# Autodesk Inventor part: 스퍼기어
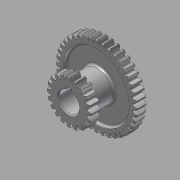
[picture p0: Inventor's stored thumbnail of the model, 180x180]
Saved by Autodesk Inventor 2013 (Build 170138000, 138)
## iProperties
Created: 2015-09
Part Number: 스퍼기어
Material: 강철, 연강
Document SubType Name: Modeling
Designer: mduedu
Density: 1 g/cm^3
Author: mduedu
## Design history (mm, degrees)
sketch "스케치1"
  geometry: C1 r 38 at (0, 0); C2 r 40 at (0, 0); C3 r 35.5 at (0, 0); 1 further point
  constraints: 3 centre point, 3 coincident
  dimensions: "d0" = 76 diameter of C1; "d2" = 2 radial gap between concentric circles of C2 C1; "d3" = 71 diameter of C3 (computed from d0)
extrude "돌출1" new body sketch "스케치1" stored distance "d4" = 10; taper "d5" = 0 deg
sketch "스케치2"
  geometry: L1 (0, 35.5)-(0, -35.5); L2 (0, 0)-(40, 0); L3 (0, 0.57)-(39.996, 0.57); L4 (0, 1.57)-(39.969, 1.57); L5 (0, 2.07)-(39.946, 2.07); A1 r 35.5 centre (0, 0) between (0, 35.5) and (0, -35.5) reference; A2 r 40 centre (0, 0) between (40, 0) and (39.946, 2.07) reference; A3 r 9.234 centre (34.93, -7.149) between (39.996, 0.57) and (35.44, 2.07); A4 r 9.234 centre (34.93, 7.149) between (35.44, -2.07) and (39.996, -0.57); A5 r 40 centre (0, 0) between (39.996, -0.57) and (39.996, 0.57); A6 r 35.5 centre (0, 0) between (35.44, -2.07) and (35.44, 2.07); 4 further points
  constraints: 16 point on circle, 10 end point, 6 point on line, 4 centre point, 3 coincident, 3 parallel, 3 symmetric about line, 2 midpoint, 1 perpendicular, 1 vertical, 3 other
  dimensions: "d6" = 0.5 distance between parallel lines of L4 L5; "d8" = 1 distance between parallel lines of L3 L4; "d9" = 1.57 distance between parallel lines of L2 L4
extrude "돌출2" join sketch "스케치2" distance "d10" = 5; taper "d12" = 0 deg; dims "d11" = 5, "d13" = 0
fillet "모깎기1" dims "d17" = 0.5
chamfer "모따기1" distance "d21" = 1; stored, may be unused: second distance "d22" = 2, angle "d23" = 45 deg
sketch "스케치3"
  geometry: C1 r 32.5 at (0, 0); C2 r 15 at (0, 0); 1 further point
  constraints: 2 centre point, 2 coincident
  dimensions: "d27" = 65 diameter of C1; "d28" = 30 diameter of C2
extrude "돌출3" cut sketch "스케치3" distance "d29" = 3; taper "d30" = 0 deg
fillet "모깎기2" dims "d31" = 2
node "작업 평면2"
  node "작업 평면1"
sketch "스케치4"
  geometry: C1 r 15 at (0, 0) reference; 1 further point
extrude "돌출4" join sketch "스케치4" stored distance "d34" = 3; taper "d35" = 0 deg
sketch "스케치5"
  geometry: C1 r 17.5 at (0, 0); C2 r 20 at (0, 0); C3 r 22 at (0, 0); 1 further point
  constraints: 3 centre point, 3 coincident
  dimensions: "d36" = 40 diameter of C2; "d38" = 2 radial gap between concentric circles of C2 C3; "d39" = 35 diameter of C1 (= d36 - 2.5 x d38)
extrude "돌출6" join sketch "스케치5" distance "d46" = 10; taper "d47" = 0 deg
sketch "스케치6"
  geometry: L1 (0, 0)-(0, 22); L2 (-17.5, 0)-(17.5, 0); L3 (-0.57, 0)-(-0.57, 21.993); L4 (-1.57, 0)-(-1.57, 21.944); L5 (-2.07, 0)-(-2.07, 21.902); A1 r 22 centre (0, 0) between (0, 22) and (-0.57, 21.993) reference; A2 r 17.5 centre (0, 0) between (-17.5, 0) and (17.5, 0) reference; A3 r 9.431 centre (7.348, 16.868) between (-0.57, 21.993) and (-2.07, 17.377); A4 r 9.431 centre (-7.348, 16.868) between (2.07, 17.377) and (0.57, 21.993); A5 r 17.5 centre (0, 0) between (2.07, 17.377) and (-2.07, 17.377); A6 r 22 centre (0, 0) between (0.57, 21.993) and (-0.57, 21.993); 4 further points
  constraints: 16 point on circle, 10 end point, 5 point on line, 4 centre point, 3 coincident, 3 symmetric about line, 2 parallel, 2 perpendicular, 1 midpoint, 1 vertical, 3 other
  dimensions: "d40" = 0.5 distance between parallel lines of L4 L5; "d42" = 1 distance between parallel lines of L3 L4; "d43" = 1.57 distance between parallel lines of L1 L4
extrude "돌출5" join sketch "스케치6" distance "d44" = 10; taper "d45" = 0 deg
fillet "모깎기3" dims "d48" = 0.5
chamfer "모따기2" distance "d49" = 1; stored, may be unused: second distance "d50" = 2, angle "d51" = 45 deg
sketch "스케치7"
  geometry: C1 r 10 at (0, 0); 1 further point
  constraints: 1 centre point, 1 coincident
  dimensions: "d55" = 20 diameter of C1
extrude "돌출7" cut sketch "스케치7" stored distance "d56" = 10; taper "d57" = 0 deg
sketch "스케치8"
  geometry: L1 (-9.539, -3)-(-12.8, -3); L2 (-12.8, -3)-(-12.8, 3); L3 (-12.8, 3)-(-9.539, 3); L4 (-9.539, 3)-(-9.539, -3); A1 r 10 centre (0, 0) between (-9.539, -3) and (-9.539, 3) reference; 2 further points
  constraints: 8 end point, 3 point on circle, 2 parallel, 1 horizontal, 1 horizontal alignment, 1 perpendicular
  dimensions: "d58" = 6 distance of L1.end L2.end; "d60" = 22.8 distance from line of point (10, 0) L2
extrude "돌출8" cut sketch "스케치8" stored distance "d61" = 10; taper "d62" = 0 deg
chamfer "모따기3" distance "d63" = 1; stored, may be unused: second distance "d64" = 2, angle "d65" = 45 deg
fillet "모깎기4" dims "d66" = 2
node "솔리드1"
pattern_circular "원형 패턴3" dims "d25" = 360 deg
mirror "대칭1"
pattern_circular "원형 패턴4" dims "d53" = 360 deg
other parameters: "d32" = 5, "d33" = 42
